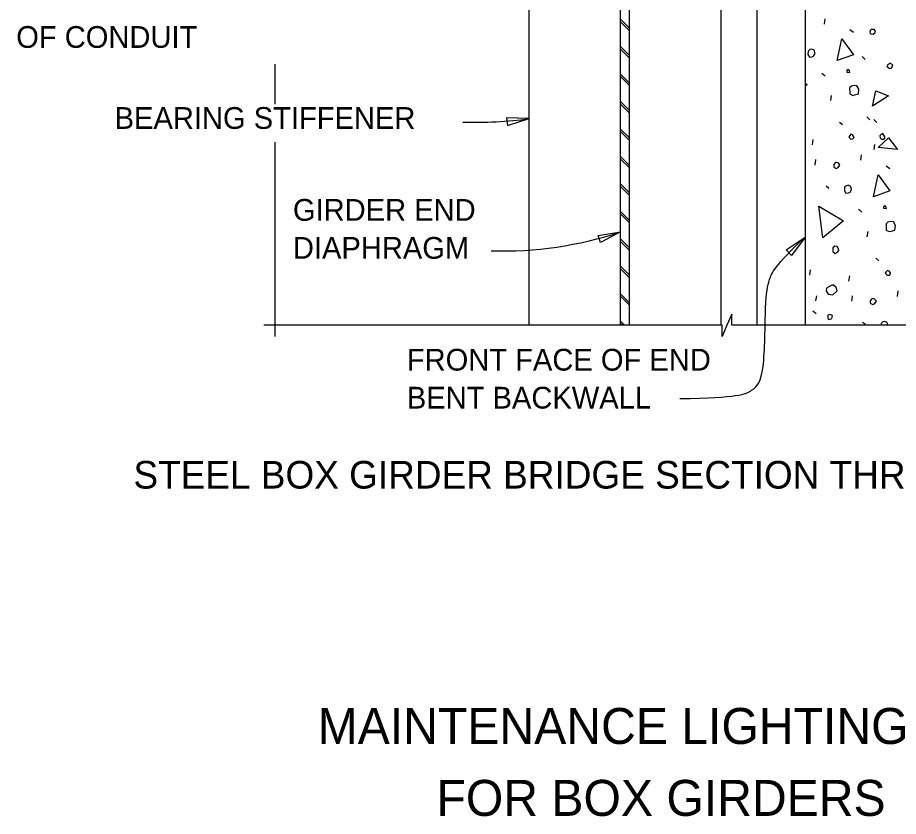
# Model space of a CAD drawing. Extents: x -1660015.2 to -1659984.9, y 2580594.2 to 2580616.7.
# Drawn here: x -1659994.44 to -1659988.32, y 2580594.35 to 2580599.91 of the extents above; entities that cross this region are included whole.
import ezdxf

# ---------------------------------------------------------------- set-up
doc = ezdxf.new("R2010")
doc.units = 0
for name, color, linetype in [('Miscellaneous', 7, 'Continuous'), ('Miscellaneous3', 7, 'Continuous'), ('Miscellaneous4', 7, 'Continuous'), ('PlotBorder_dp', 7, 'Continuous'), ('SheetLines_dp', 7, 'Continuous'), ('SteelGirder', 7, 'Continuous')]:
    doc.layers.add(name, color=color, linetype=linetype)

msp = doc.modelspace()

# ---------------------------------------------------------------- linework, layer by layer
at = {"layer": 'Miscellaneous'}
for p, q in [((-1659990.1908, 2580599.8327), (-1659990.2531, 2580599.8951)), ((-1659990.1908, 2580599.815), (-1659990.2531, 2580599.8774)), ((-1659988.8378, 2580599.8607), (-1659988.8324, 2580599.8984)), ((-1659988.6619, 2580599.8225), (-1659988.6361, 2580599.8035)), ((-1659990.1908, 2580599.6418), (-1659990.2531, 2580599.7042)), ((-1659990.1908, 2580599.6241), (-1659990.2531, 2580599.6865)), ((-1659988.5757, 2580599.6359), (-1659988.5548, 2580599.6156)), ((-1659990.1908, 2580599.4509), (-1659990.2531, 2580599.5133)), ((-1659990.1908, 2580599.4332), (-1659990.2531, 2580599.4956)), ((-1659988.8551, 2580599.5196), (-1659988.8318, 2580599.5)), ((-1659988.7937, 2580599.329), (-1659988.7876, 2580599.3643)), ((-1659990.1908, 2580599.2599), (-1659990.2531, 2580599.3223)), ((-1659990.1908, 2580599.2423), (-1659990.2531, 2580599.3047)), ((-1659988.733, 2580599.1797), (-1659988.7127, 2580599.1618)), ((-1659988.5432, 2580599.215), (-1659988.5222, 2580599.1947)), ((-1659988.4943, 2580599.197), (-1659988.4734, 2580599.1768)), ((-1659990.1908, 2580599.069), (-1659990.2531, 2580599.1314)), ((-1659990.1908, 2580599.0513), (-1659990.2531, 2580599.1137)), ((-1659988.9207, 2580599.0207), (-1659988.9153, 2580599.0583)), ((-1659988.4926, 2580598.9878), (-1659988.4866, 2580599.0231)), ((-1659990.1908, 2580598.8781), (-1659990.2532, 2580598.9405)), ((-1659988.5842, 2580598.9141), (-1659988.5788, 2580598.9518)), ((-1659990.1908, 2580598.8604), (-1659990.2531, 2580598.9228)), ((-1659988.9014, 2580598.8809), (-1659988.896, 2580598.9186)), ((-1659988.4083, 2580598.8758), (-1659988.3825, 2580598.8569)), ((-1659990.1908, 2580598.6872), (-1659990.2531, 2580598.7496)), ((-1659990.1908, 2580598.6695), (-1659990.2531, 2580598.7319)), ((-1659988.8262, 2580598.7354), (-1659988.8065, 2580598.72)), ((-1659990.1908, 2580598.4963), (-1659990.2531, 2580598.5587)), ((-1659988.6015, 2580598.573), (-1659988.5781, 2580598.5534)), ((-1659990.1908, 2580598.4786), (-1659990.2531, 2580598.541)), ((-1659988.5401, 2580598.3824), (-1659988.534, 2580598.4177)), ((-1659990.1908, 2580598.3054), (-1659990.2531, 2580598.3677)), ((-1659990.1908, 2580598.2877), (-1659990.2531, 2580598.3501)), ((-1659988.4793, 2580598.2331), (-1659988.459, 2580598.2152)), ((-1659990.1908, 2580598.1144), (-1659990.2531, 2580598.1768)), ((-1659990.1908, 2580598.0968), (-1659990.2531, 2580598.1591)), ((-1659988.9395, 2580598.1149), (-1659988.934, 2580598.1526)), ((-1659988.6671, 2580598.074), (-1659988.6617, 2580598.1117)), ((-1659990.1908, 2580597.9235), (-1659990.2531, 2580597.9859)), ((-1659990.1908, 2580597.9058), (-1659990.2531, 2580597.9682)), ((-1659988.897, 2580597.9374), (-1659988.891, 2580597.9726)), ((-1659988.6478, 2580597.9343), (-1659988.6423, 2580597.972)), ((-1659988.3305, 2580597.9675), (-1659988.3251, 2580598.0052)), ((-1659988.9171, 2580597.8673), (-1659988.8937, 2580597.8477)), ((-1659990.2253, 2580597.7672), (-1659990.2531, 2580597.795)), ((-1659990.243, 2580597.7672), (-1659990.2531, 2580597.7773)), ((-1659988.5725, 2580597.7888), (-1659988.5529, 2580597.7734))]:
    msp.add_line(p, q, dxfattribs=at)
for points in [[(-1659988.5202, 2580599.7957), (-1659988.5141, 2580599.7922), (-1659988.4983, 2580599.7913), (-1659988.4857, 2580599.8024), (-1659988.4828, 2580599.8109), (-1659988.4916, 2580599.8241), (-1659988.5122, 2580599.8238), (-1659988.5205, 2580599.8163), (-1659988.5228, 2580599.8054), (-1659988.5202, 2580599.7957)], [(-1659988.7493, 2580599.6075), (-1659988.7173, 2580599.7585), (-1659988.636, 2580599.6482), (-1659988.7493, 2580599.6075)], [(-1659988.9505, 2580599.6727), (-1659988.9519, 2580599.649), (-1659988.9419, 2580599.631), (-1659988.9244, 2580599.6331), (-1659988.9129, 2580599.6387), (-1659988.9023, 2580599.6571), (-1659988.9081, 2580599.6788), (-1659988.9259, 2580599.687), (-1659988.9379, 2580599.6838), (-1659988.9505, 2580599.6727)], [(-1659988.6812, 2580599.5274), (-1659988.66, 2580599.5253), (-1659988.6626, 2580599.535), (-1659988.6706, 2580599.5458), (-1659988.6814, 2580599.5377), (-1659988.6812, 2580599.5274)], [(-1659988.4011, 2580599.5637), (-1659988.3827, 2580599.5531), (-1659988.3682, 2580599.5569), (-1659988.3631, 2580599.5764), (-1659988.3821, 2580599.5894), (-1659988.3905, 2580599.582), (-1659988.3995, 2580599.577), (-1659988.4011, 2580599.5637), (-1659988.4024, 2580599.5685)], [(-1659988.972, 2580599.4485), (-1659988.9581, 2580599.4403), (-1659988.972, 2580599.4288)], [(-1659988.6624, 2580599.4186), (-1659988.6611, 2580599.3749), (-1659988.6403, 2580599.365), (-1659988.6282, 2580599.3682), (-1659988.6016, 2580599.3753), (-1659988.5973, 2580599.4075), (-1659988.6117, 2580599.4322), (-1659988.6305, 2580599.4349), (-1659988.6499, 2580599.4297), (-1659988.6624, 2580599.4186)], [(-1659988.5038, 2580599.2903), (-1659988.4807, 2580599.3974), (-1659988.3934, 2580599.3612), (-1659988.5038, 2580599.2903)], [(-1659988.6688, 2580599.0752), (-1659988.6546, 2580599.0609), (-1659988.6394, 2580599.0624), (-1659988.6317, 2580599.0722), (-1659988.633, 2580599.077), (-1659988.6417, 2580599.0902), (-1659988.6533, 2580599.0949), (-1659988.661, 2580599.0851), (-1659988.6688, 2580599.0752)], [(-1659988.4632, 2580599.0035), (-1659988.3927, 2580599.069), (-1659988.3302, 2580598.99), (-1659988.4632, 2580599.0035)], [(-1659988.4497, 2580599.0692), (-1659988.4399, 2580599.0615), (-1659988.4265, 2580599.0599), (-1659988.4182, 2580599.0673), (-1659988.4184, 2580599.0776), (-1659988.424, 2580599.089), (-1659988.4321, 2580599.0998), (-1659988.4453, 2580599.0911), (-1659988.4536, 2580599.0837), (-1659988.4497, 2580599.0692)], [(-1659988.7729, 2580598.8843), (-1659988.7732, 2580598.8661), (-1659988.7555, 2580598.8579), (-1659988.7416, 2580598.8642), (-1659988.7304, 2580598.8801), (-1659988.7384, 2580598.8909), (-1659988.7452, 2580598.8969), (-1659988.7562, 2580598.8991), (-1659988.761, 2580598.8978), (-1659988.7729, 2580598.8843)], [(-1659988.4956, 2580598.6609), (-1659988.4636, 2580598.8119), (-1659988.3823, 2580598.7016), (-1659988.4956, 2580598.6609)], [(-1659988.6969, 2580598.7261), (-1659988.6983, 2580598.7024), (-1659988.6883, 2580598.6844), (-1659988.6707, 2580598.6865), (-1659988.6593, 2580598.6921), (-1659988.6487, 2580598.7105), (-1659988.6545, 2580598.7322), (-1659988.6722, 2580598.7404), (-1659988.6843, 2580598.7372), (-1659988.6969, 2580598.7261)], [(-1659988.8486, 2580598.3748), (-1659988.8766, 2580598.5951), (-1659988.7045, 2580598.4937), (-1659988.8486, 2580598.3748)], [(-1659988.4276, 2580598.5808), (-1659988.4063, 2580598.5787), (-1659988.4089, 2580598.5884), (-1659988.417, 2580598.5992), (-1659988.4278, 2580598.5911), (-1659988.4276, 2580598.5808)], [(-1659988.4088, 2580598.472), (-1659988.4074, 2580598.4283), (-1659988.3866, 2580598.4184), (-1659988.3746, 2580598.4216), (-1659988.348, 2580598.4287), (-1659988.3437, 2580598.4609), (-1659988.3581, 2580598.4856), (-1659988.3769, 2580598.4883), (-1659988.3962, 2580598.4831), (-1659988.4088, 2580598.472)], [(-1659988.7788, 2580598.2978), (-1659988.7791, 2580598.2796), (-1659988.7625, 2580598.2659), (-1659988.7469, 2580598.2753), (-1659988.7367, 2580598.2857), (-1659988.74, 2580598.2978), (-1659988.7493, 2580598.3134), (-1659988.7658, 2580598.3168), (-1659988.7783, 2580598.3056), (-1659988.7788, 2580598.2978)], [(-1659988.4151, 2580598.1286), (-1659988.4009, 2580598.1143), (-1659988.3858, 2580598.1158), (-1659988.3781, 2580598.1256), (-1659988.3794, 2580598.1304), (-1659988.3881, 2580598.1436), (-1659988.3997, 2580598.1483), (-1659988.4074, 2580598.1385), (-1659988.4151, 2580598.1286)], [(-1659988.8248, 2580598.0059), (-1659988.8111, 2580597.9837), (-1659988.7789, 2580597.9794), (-1659988.7496, 2580598.0053), (-1659988.7561, 2580598.0295), (-1659988.7733, 2580598.0456), (-1659988.7861, 2580598.0448), (-1659988.8065, 2580598.0341), (-1659988.8221, 2580598.0247), (-1659988.8248, 2580598.0059)], [(-1659988.5192, 2580597.9377), (-1659988.5195, 2580597.9195), (-1659988.5018, 2580597.9113), (-1659988.488, 2580597.9176), (-1659988.4767, 2580597.9335), (-1659988.4848, 2580597.9443), (-1659988.4916, 2580597.9503), (-1659988.5025, 2580597.9525), (-1659988.5073, 2580597.9512), (-1659988.5192, 2580597.9377)], [(-1659988.8145, 2580597.8223), (-1659988.8106, 2580597.8078), (-1659988.7979, 2580597.8087), (-1659988.7864, 2580597.8143), (-1659988.7806, 2580597.8314), (-1659988.7874, 2580597.8373), (-1659988.799, 2580597.842), (-1659988.8135, 2580597.8381), (-1659988.8145, 2580597.8223)], [(-1659988.4432, 2580597.7795), (-1659988.4439, 2580597.7673)], [(-1659988.3959, 2580597.7673), (-1659988.4009, 2580597.7856), (-1659988.4186, 2580597.7938), (-1659988.4307, 2580597.7906), (-1659988.4432, 2580597.7795)]]:
    msp.add_lwpolyline(points, dxfattribs=at)
at = {"layer": 'Miscellaneous3'}
msp.add_line((-1659988.972, 2580602.2354), (-1659988.972, 2580597.7672), dxfattribs=at)
at = {"layer": 'SheetLines_dp'}
for points in [[(-1659992.6544, 2580599.3033), (-1659992.6544, 2580599.5821)], [(-1659992.6544, 2580597.6896), (-1659992.6544, 2580599.0391)], [(-1659986.1909, 2580597.7671), (-1659989.4814, 2580597.7671), (-1659989.4814, 2580597.8446), (-1659989.5152, 2580597.7671), (-1659989.5489, 2580597.6896), (-1659989.5489, 2580597.7671), (-1659992.7319, 2580597.7671)]]:
    msp.add_lwpolyline(points, dxfattribs=at)
for points in [[(-1659990.8887, 2580599.2034), (-1659991.047, 2580599.208), (-1659991.0397, 2580599.1556)], [(-1659990.2532, 2580598.4154), (-1659990.3934, 2580598.3418), (-1659990.4099, 2580598.3921)], [(-1659988.9719, 2580598.3798), (-1659989.0658, 2580598.2523), (-1659989.1026, 2580598.2903)]]:
    msp.add_lwpolyline(points, close=True, dxfattribs=at)
for centre, start, end in [((-1659991.2519, 2580601.8052), 267.88954, 277.94853), ((-1659991.0761, 2580600.9103), 268.34066, 288.25581)]:
    msp.add_arc(centre, 2.6271, start, end, dxfattribs=at)
msp.add_open_spline([(-1659989.8417, 2580597.2571), (-1659989.4354, 2580597.2624), (-1659989.3301, 2580597.3126), (-1659989.2504, 2580597.4019), (-1659989.2504, 2580597.9574), (-1659989.224, 2580598.0801), (-1659989.1863, 2580598.1782), (-1659988.9719, 2580598.3798)], degree=3, dxfattribs=at)
at = {"layer": 'SteelGirder'}
for p, q in [((-1659989.3053, 2580597.7672), (-1659989.3053, 2580602.2354)), ((-1659990.2532, 2580597.7672), (-1659990.2532, 2580602.152)), ((-1659990.1908, 2580597.7672), (-1659990.1908, 2580602.152)), ((-1659989.5553, 2580597.7672), (-1659989.5553, 2580601.9948)), ((-1659990.8887, 2580597.7672), (-1659990.8887, 2580601.1344))]:
    msp.add_line(p, q, dxfattribs=at)

# ---------------------------------------------------------------- texts
at = {"layer": 'Miscellaneous4'}
for s, p in [('MAINTENANCE LIGHTING', (-1659992.3581, 2580594.8559)), ('FOR BOX GIRDERS', (-1659991.5328, 2580594.3559))]:
    msp.add_text(s, height=0.25001, rotation=360, dxfattribs=at).set_placement(p)
at = {"layer": 'PlotBorder_dp'}
for s, height, p in [('BEARING STIFFENER', 0.1512, (-1659993.7685, 2580599.1323)), ('STEEL BOX GIRDER BRIDGE SECTION THRU END BENTS', 0.192, (-1659993.6377, 2580596.6316))]:
    msp.add_text(s, height=height, dxfattribs=at).set_placement(p)
at = {"layer": 'SheetLines_dp'}
for s, p in [('OF CONDUIT', (-1659994.4521, 2580599.6956)), ('GIRDER END', (-1659992.5299, 2580598.4933)), ('DIAPHRAGM', (-1659992.5299, 2580598.2293)), ('FRONT FACE OF END ', (-1659991.7384, 2580597.4518)), ('BENT BACKWALL', (-1659991.7384, 2580597.1878))]:
    msp.add_text(s, height=0.1512, dxfattribs=at).set_placement(p)

doc.saveas('drawing.dxf')
